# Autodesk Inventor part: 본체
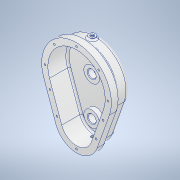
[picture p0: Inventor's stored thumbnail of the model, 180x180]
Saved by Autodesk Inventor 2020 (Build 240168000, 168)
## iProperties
Created: 2024-05
Part Number: 본체
Material: 알루미늄 6061
Document SubType Name: Modeling
Designer: oem
Density: 2.7 g/cm^3
Appearance: 알루미늄 - 평지
Mass: 508.765 g
Surface Area: 657.559 cm^2
Volume: 188.431 cm^3
Author: oem
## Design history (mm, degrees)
sketch "스케치1"
  geometry: L1 (0, 34)-(0, -35); L2 (-36.77, -48)-(-58.454, 13.333); L3 (36, -50.177)-(58.454, 13.333); A1 r 62 centre (0, 34) between (58.454, 13.333) and (-58.454, 13.333); A2 r 39 centre (0, -35) between (-36.77, -48) and (36.77, -48); 1 further point
  constraints: 6 end point, 4 point on circle, 4 tangent, 2 centre point, 2 coincident, 1 point on line, 1 vertical, 1 vertical alignment
  dimensions: "d3" = 62 radius of A1; "d4" = 39 radius of A2; "d134" = 34 distance of L1.start point (0, 0)
extrude "돌출1" new body sketch "스케치1" distance "d5" = 15; taper "d6" = 0 deg
sketch "스케치2"
  geometry: L1 (58.454, 13.333)-(36.77, -48) reference; L2 (-52.797, 15.333)-(-31.113, -46); L3 (31.113, -46)-(52.797, 15.333); A1 r 62 centre (0, 34) between (58.454, 13.333) and (-58.454, 13.333) reference; A2 r 39 centre (0, -35) between (-36.77, -48) and (36.77, -48) reference; A3 r 56 centre (0, 34) between (52.797, 15.333) and (-52.797, 15.333); A4 r 33 centre (0, -35) between (-31.113, -46) and (31.113, -46); 1 further point
  constraints: 4 end point, 4 point on circle, 3 tangent, 2 centre point, 2 coincident, 1 parallel
  dimensions: "d9" = 56 radius of A3; "d10" = 33 radius of A4
extrude "돌출2" join sketch "스케치2" distance "d11" = 25; taper "d12" = 0 deg
fillet "모깎기1" dims "d13" = 8
fillet "모깎기2" dims "d14" = 3
sketch "스케치3"
  geometry: C1 r 15 at (0, 34); A1 r 48 centre (0, 34) between (45.255, 18) and (-45.255, 18) reference; 1 further point
  constraints: 1 centre point, 1 coincident
  dimensions: "d16" = 30 diameter of C1
extrude "돌출3" join sketch "스케치3" distance "d17" = 8; taper "d18" = 0 deg
sketch "스케치4"
  geometry: C1 r 15 at (0, -35); A1 r 25 centre (0, -35) between (-23.57, -43.334) and (23.57, -43.334) reference; 1 further point
  constraints: 1 centre point, 1 coincident
  dimensions: "d19" = 30 diameter of C1
extrude "돌출4" join sketch "스케치4" distance "d20" = 8; taper "d21" = 0 deg
node "작업 평면1"
sketch "스케치12"
  geometry: C1 r 15 at (0, 34) reference; 2 further points
  constraints: 1 vertical alignment, 1 other
  dimensions: "d51" = 30 distance of C1.centre point (0, 64)
feature "엠보싱1" sketch "스케치12" dims "d52" = 0.5, "d53" = 0
sketch "스케치13"
  geometry: L1 (-26.399, -44.334)-(-48.083, 17); L2 (48.083, 17)-(26.399, -44.334); A1 r 39 centre (0, -35) between (-36.77, -48) and (36.77, -48) reference; A2 r 62 centre (0, 34) between (58.454, 13.333) and (-58.454, 13.333) reference; A3 r 28 centre (0, -35) between (-26.399, -44.334) and (26.399, -44.334); A4 r 51 centre (0, 34) between (48.083, 17) and (-48.083, 17); 1 further point
  constraints: 4 end point, 4 point on circle, 4 tangent, 2 centre point, 2 coincident
  dimensions: "d56" = 51 radius of A4; "d57" = 28 radius of A3
extrude "돌출7" cut sketch "스케치13" distance "d58" = 35; taper "d59" = 0 deg
sketch "스케치14"
  geometry: C1 r 14 at (0, 34); A1 r 51 centre (0, 34) between (48.083, 17) and (-48.083, 17) reference; 1 further point
  constraints: 1 centre point, 1 coincident
  dimensions: "d60" = 28 diameter of C1
extrude "돌출8" join sketch "스케치14" distance "d61" = 8; taper "d62" = 0 deg
sketch "스케치15"
  geometry: C1 r 14 at (0, -35); A1 r 28 centre (0, -35) between (-26.399, -44.334) and (26.399, -44.334) reference; 1 further point
  constraints: 1 centre point, 1 coincident
  dimensions: "d64" = 28 diameter of C1
extrude "돌출9" join sketch "스케치15" distance "d65" = 8; taper "d66" = 0 deg
fillet "모깎기3" dims "d67" = 3
sketch "스케치16"
  geometry: C1 r 15 at (0, 0) reference; 2 further points
  constraints: 1 coincident
hole "구멍4" sketch "스케치16" at (0, 0) diameter "d68" = 14; stored, may be unused: countersink angle "d72" = 90 deg, drill point angle "d74" = 0 deg; dims "d69" = 24, "d70" = 20, "d71" = 4.2, "d73" = 10
sketch "스케치17"
  geometry: C1 r 14 at (0, 0) reference; 2 further points
  constraints: 1 coincident
hole "구멍5" sketch "스케치17" at (0, 0) diameter "d75" = 14; stored, may be unused: countersink angle "d79" = 90 deg, drill point angle "d81" = 0 deg; dims "d76" = 24, "d77" = 20, "d78" = 4.2, "d80" = 10
sketch "스케치18"
  geometry: L1 (-31.113, -46)-(-52.797, 15.333); L2 (31.113, -46)-(52.797, 15.333); L3 (0, 34)-(0, 90); L4 (0, 34)-(39.598, 73.598); L5 (0, 34)-(-39.598, 73.598); L6 (52.797, 15.333)-(31.113, -46) reference; L7 (-31.113, -46)-(-52.797, 15.333) reference; C1 r 7 at (0, 34) reference; A1 r 51 centre (0, 34) between (48.083, 17) and (-48.083, 17) reference; A2 r 28 centre (0, -35) between (-26.399, -44.334) and (26.399, -44.334) reference; A3 r 39 centre (0, -35) between (-36.77, -48) and (36.77, -48) reference; A4 r 33 centre (0, -35) between (-31.113, -46) and (31.113, -46) reference; A5 r 56 centre (0, 34) between (52.797, 15.333) and (-52.797, 15.333) reference; A6 r 33 centre (0, -35) between (-31.113, -46) and (31.113, -46); A7 r 56 centre (0, 34) between (52.797, 15.333) and (-52.797, 15.333); 11 further points
  constraints: 10 end point, 10 point on circle, 6 horizontal alignment, 5 coincident, 4 point on line, 3 tangent, 2 centre point
  dimensions: "d84" = 45 deg angle of L5 L3; "d85" = 45 deg angle of L3 L4
hole "구멍6" sketch "스케치18" at (-39.598, 73.598), (39.598, 73.598), (0, 90), (-56, 34), (56, 34), (35.002, -35), (-47.376, 0), (0, -68), (47.376, 0), (-35.002, -35) diameter "d86" = 3.242; stored, may be unused: countersink angle "d90" = 90 deg, drill point angle "d92" = 118 deg; dims "d87" = 8, "d88" = 20, "d89" = 4.2, "d91" = 10
node "작업 평면2"
sketch "스케치19"
  geometry: L1 (62, 0)-(-62, 0) reference; L2 (62, 15)-(-62, 15) reference; C1 r 6 at (0, -13); 6 further points
  constraints: 1 centre point, 1 midpoint, 1 vertical alignment
  dimensions: "d94" = 12 diameter of C1; "d95" = 28 distance from line of C1.centre L2
extrude "돌출10" join sketch "스케치19" stored distance "d96" = 8; taper "d97" = 0 deg
sketch "스케치20"
  geometry: C1 r 6 at (0, 0) reference; 2 further points
  constraints: 1 coincident
hole "구멍7" sketch "스케치20" at (0, 0) diameter "d98" = 5.1881; stored, may be unused: countersink angle "d102" = 90 deg, drill point angle "d104" = 0 deg; dims "d99" = 24.75, "d100" = 7, "d101" = 2, "d103" = 25.75
node "작업 평면3"
sketch "스케치21"
  geometry: L1 (-36.77, 15)-(36.77, 15) reference; L2 (-36.77, 0)-(36.77, 0) reference; C1 r 6 at (0, -13); 2 further points
  constraints: 1 centre point, 1 midpoint, 1 vertical alignment
  dimensions: "d106" = 12 diameter of C1; "d107" = 28 distance from line of L1 C1.centre
extrude "돌출11" join sketch "스케치21" stored distance "d108" = 8; taper "d109" = 0 deg
sketch "스케치22"
  geometry: C1 r 6 at (0, 0) reference; 2 further points
  constraints: 1 coincident
hole "구멍8" sketch "스케치22" at (0, 0) diameter "d110" = 5.1881; stored, may be unused: countersink angle "d114" = 90 deg, drill point angle "d116" = 0 deg; dims "d111" = 13.75, "d112" = 7, "d113" = 2, "d115" = 15.25
chamfer "모따기1" distance "d117" = 1; stored, may be unused: second distance "d118" = 2, angle "d119" = 45 deg
fillet "모깎기4" dims "d121" = 3
chamfer "모따기2" distance "d122" = 0.4; stored, may be unused: second distance "d123" = 2, angle "d124" = 30 deg
sketch "스케치24"
  geometry: L1 (41, -22)-(27, -22) reference; L2 (34, -22)-(38, -22); L3 (38, -22)-(34, -24.309); L4 (34, -24.309)-(34, -22); 1 further point
  constraints: 6 end point, 1 midpoint, 1 perpendicular, 1 point on line
  dimensions: "d127" = 60 deg angle of L3 L4; "d128" = 8 diameter of L2.end L4
revolve "회전1" sketch "스케치24" stored, may be unused: angle "d129" = 90 deg
fillet "모깎기5" dims "d130" = 3
fillet "모깎기6" dims "d131" = 3
fillet "모깎기7" dims "d132" = 3
fillet "모깎기8" dims "d133" = 3
fillet "모깎기9" dims "d135" = 0.1
node "솔리드1"
node "투영된 루프1"
feature "A9D066F2-1C7D-4E18-AEED-F7BC21143FA4" dims "d68" = 14, "d69" = 24, "d70" = 20, "d71" = 4.2, "d72" = 90 deg, "d73" = 10, "d74" = 0
other parameters: "d1" = 124, "d2" = 78, "d7" = 112, "d8" = 66, "d54" = 102, "d55" = 56, "d82" = 112, "d83" = 66, "d93" = 93, "d105" = -71
